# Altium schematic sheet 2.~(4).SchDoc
size 420 x 297 mm
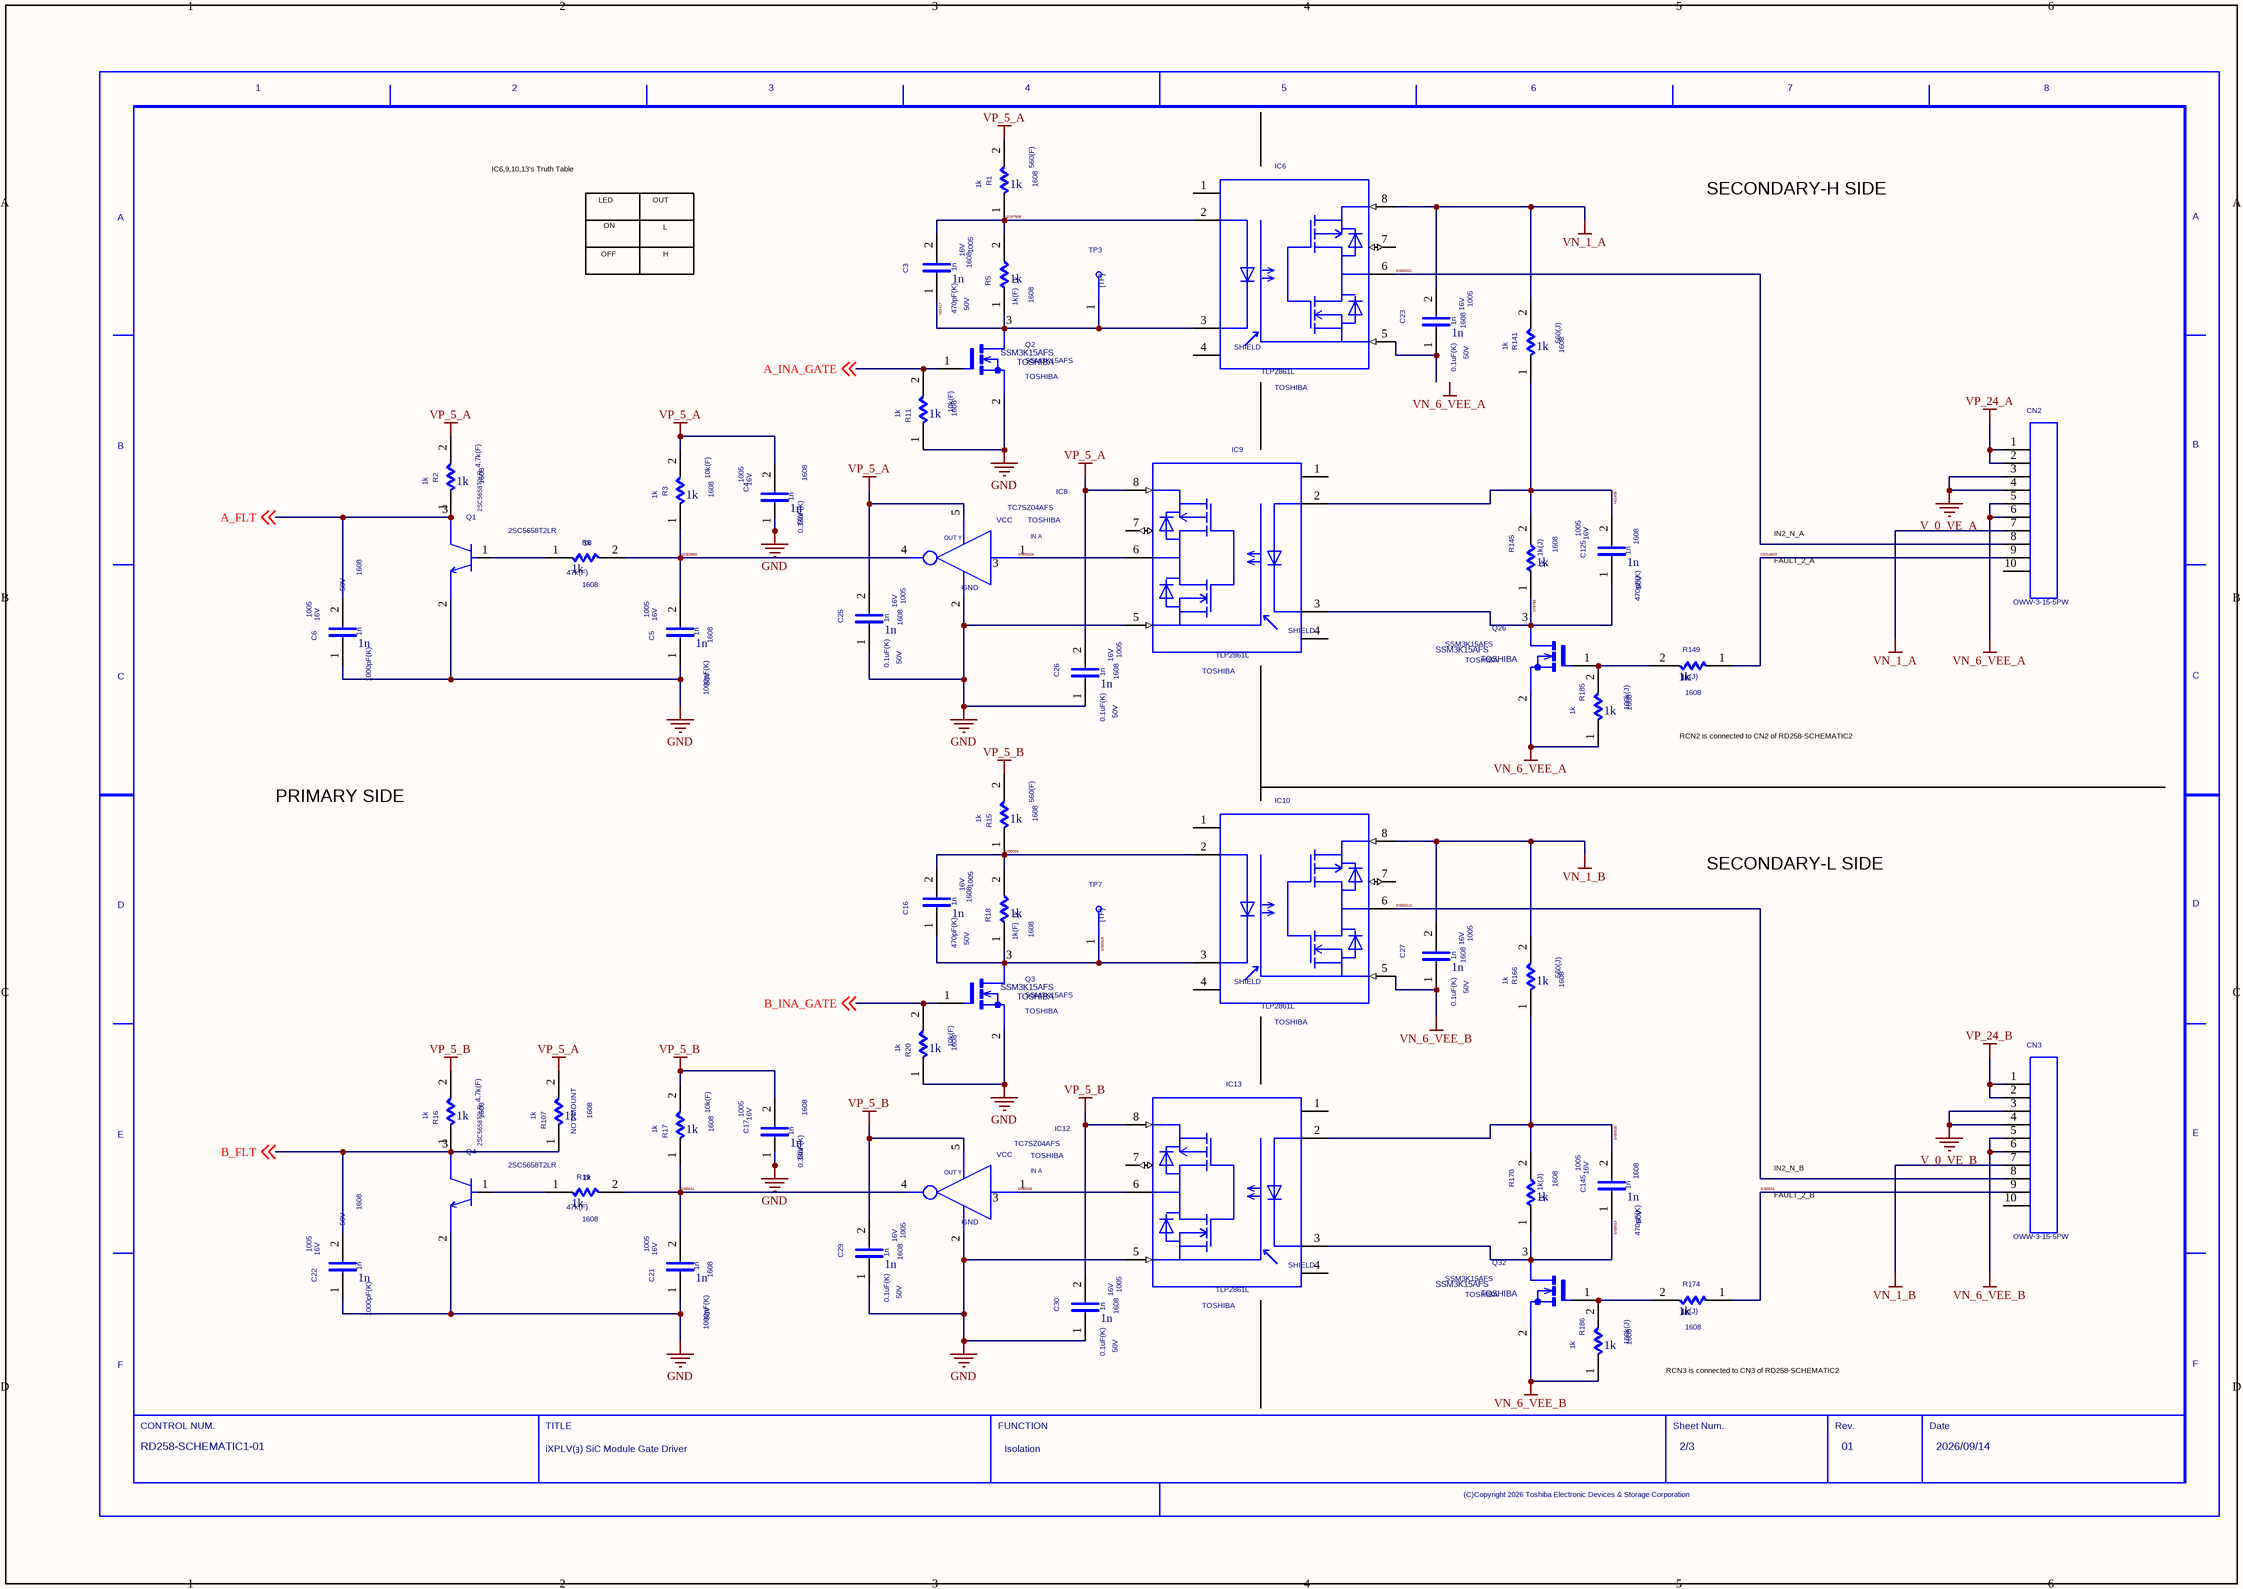
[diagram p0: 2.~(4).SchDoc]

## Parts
C3  1n  VAL1: 470pF(K)  SIZE: 1005  VOLTAGE: 16V  SIZECODESMD: 1608  VAL2: 50V
C4  1n  VAL1: 0.33uF(K)  SIZE: 1005  VOLTAGE: 16V  SIZECODESMD: 1608  VAL2: 50V
C5  1n  VAL1: 1000pF(K)  SIZE: 1005  VOLTAGE: 16V  SIZECODESMD: 1608  VAL2: 50V
C6  1n  VAL1: 1000pF(K)  SIZE: 1005  VOLTAGE: 16V  SIZECODESMD: 1608  VAL2: 50V
C16  1n  VAL1: 470pF(K)  SIZE: 1005  VOLTAGE: 16V  SIZECODESMD: 1608  VAL2: 50V
C17  1n  VAL1: 0.33uF(K)  SIZE: 1005  VOLTAGE: 16V  SIZECODESMD: 1608  VAL2: 50V
C21  1n  VAL1: 1000pF(K)  SIZE: 1005  VOLTAGE: 16V  SIZECODESMD: 1608  VAL2: 50V
C22  1n  VAL1: 1000pF(K)  SIZE: 1005  VOLTAGE: 16V  SIZECODESMD: 1608  VAL2: 50V
C23  1n  VAL1: 0.1uF(K)  SIZE: 1005  VOLTAGE: 16V  SIZECODESMD: 1608  VAL2: 50V
C25  1n  VAL1: 0.1uF(K)  SIZE: 1005  VOLTAGE: 16V  SIZECODESMD: 1608  VAL2: 50V
C26  1n  VAL1: 0.1uF(K)  SIZE: 1005  VOLTAGE: 16V  SIZECODESMD: 1608  VAL2: 50V
C27  1n  VAL1: 0.1uF(K)  SIZE: 1005  VOLTAGE: 16V  SIZECODESMD: 1608  VAL2: 50V
C29  1n  VAL1: 0.1uF(K)  SIZE: 1005  VOLTAGE: 16V  SIZECODESMD: 1608  VAL2: 50V
C30  1n  VAL1: 0.1uF(K)  SIZE: 1005  VOLTAGE: 16V  SIZECODESMD: 1608  VAL2: 50V
C125  1n  VAL1: 470pF(K)  SIZE: 1005  VOLTAGE: 16V  SIZECODESMD: 1608  VAL2: 50V
C145  1n  VAL1: 470pF(K)  SIZE: 1005  VOLTAGE: 16V  SIZECODESMD: 1608  VAL2: 50V
CN2  VAL3: OWW-3-15-5PW  (hidden comment: CN9_2)
CN3  VAL3: OWW-3-15-5PW  (hidden comment: CN9_2)
IC6  USERCOMPTEXT3: TOSHIBA  (hidden comment: TLP2861L)
IC8  USERCOMPTEXT3: TOSHIBA  (hidden comment: TC7SZ04AFS)
IC9  USERCOMPTEXT3: TOSHIBA  (hidden comment: TLP2861L)
IC10  USERCOMPTEXT3: TOSHIBA  (hidden comment: TLP2861L)
IC12  USERCOMPTEXT3: TOSHIBA  (hidden comment: TC7SZ04AFS)
IC13  USERCOMPTEXT3: TOSHIBA  (hidden comment: TLP2861L)
Q1  2SC5658T2LR
Q2  SSM3K15AFS  VENDOR: TOSHIBA
Q3  SSM3K15AFS  VENDOR: TOSHIBA
Q4  2SC5658T2LR
Q26  SSM3K15AFS  VENDOR: TOSHIBA
Q32  SSM3K15AFS  VENDOR: TOSHIBA
R1  1k  VAL1: 560(F)  SIZECODESMD: 1608
R2  1k  VAL1: 4.7k(F)  SIZECODESMD: 1608
R3  1k  VAL1: 10k(F)  SIZECODESMD: 1608
R5  1k  VAL1: 1k(F)  SIZECODESMD: 1608
R8  1k  VAL1: 47k(F)  SIZECODESMD: 1608
R11  1k  VAL1: 10k(F)  SIZECODESMD: 1608
R15  1k  VAL1: 560(F)  SIZECODESMD: 1608
R16  1k  VAL1: 4.7k(F)  SIZECODESMD: 1608
R17  1k  VAL1: 10k(F)  SIZECODESMD: 1608
R18  1k  VAL1: 1k(F)  SIZECODESMD: 1608
R19  1k  VAL1: 47k(F)  SIZECODESMD: 1608
R20  1k  VAL1: 10k(F)  SIZECODESMD: 1608
R107  1k  NOTMOUNT: NOT MOUNT  SIZECODESMD: 1608
R141  1k  VAL1: 560(J)  SIZECODESMD: 1608
R145  1k  VAL1: 1k(J)  SIZECODESMD: 1608
R149  1k  VAL1: 1k(J)  SIZECODESMD: 1608
R166  1k  VAL1: 560(J)  SIZECODESMD: 1608
R170  1k  VAL1: 1k(J)  SIZECODESMD: 1608
R174  1k  VAL1: 1k(J)  SIZECODESMD: 1608
R185  1k  VAL1: 100k(J)  SIZECODESMD: 1608
R186  1k  VAL1: 100k(J)  SIZECODESMD: 1608
TP3  TP  (value not drawn)
TP7  TP  (value not drawn)
U?  DATE: 2026/09/14  DRAWINGNUMBER: RD258-SCHEMATIC1-01  TITLE: iXPLV(ｮ) SiC Module Gate Driver  FUNCTION: Isolation  SHEETNUMBER: 2/3  REVISION: 01  (hidden comment: WAKU_DEF100)

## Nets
GND: C4.1 C5.1 C6.1 C17.1 C21.1 C22.1 C25.1 C26.1 C29.1 C30.1 IC8.2 IC9.5 IC12.2 IC13.5 Q1.2(E) Q2.2(S) Q3.2(S) Q4.2(E) R11.1 R20.1
V_0_VE_A: CN2.3 CN2.4
V_0_VE_B: CN3.3 CN3.4
VN_1_A: C23.2 CN2.7 IC6.8 R141.2
VN_1_B: C27.2 CN3.7 IC10.8 R166.2
VN_6_VEE_A: CN2.5 CN2.6 Q26.2(S) R185.1
VN_6_VEE_B: C27.1 CN3.5 CN3.6 IC10.5 Q32.2(S) R186.1
VP_5_A: C4.2 C25.2 C26.2 IC8.5 IC9.8 R1.2 R2.2 R3.2 R107.2
VP_5_B: C17.2 C29.2 C30.2 IC12.5 IC13.8 R15.2 R16.2 R17.2
VP_24_A: CN2.1 CN2.2
VP_24_B: CN3.1 CN3.2
A_FLT: C6.2 Q1.3(C) R2.1 ; off-sheet A_FLT
A_INA_GATE: Q2.1(G) R11.2 ; off-sheet A_INA_GATE
B_FLT: C22.2 Q4.3(C) R16.1 R107.1 ; off-sheet B_FLT
B_INA_GATE: Q3.1(G) R20.2 ; off-sheet B_INA_GATE
N02405: C125.2 IC9.2 R141.1 R145.2
N02417: C3.1 IC6.3 Q2.3(D) R5.1 TP3.1
N76786: C125.1 IC9.3 Q26.3(D) R145.1
N2014523: CN2.9 R149.1
N2053860: C5.2 IC8.4 R3.1 R8.2
N2197908: C3.2 IC6.2 R1.1 R5.2
SIG00005: Q1.1(B) R8.1
SIG0021: C21.2 IC12.4 R17.1 R19.2
SIG00021: CN2.8 IC6.6
SIG0022: Q32.1(G) R174.2 R186.2
SIG0023: C145.1 IC13.3 Q32.3(D) R170.1
SIG0024: CN3.9 R174.1
SIG0025: C145.2 IC13.2 R166.1 R170.2
SIG00026: IC8.1 IC9.6
SIG0026: C16.2 IC10.2 R15.1 R18.2
SIG0027: Q4.1(B) R19.1
SIG0028: IC12.1 IC13.6
SIG0029: C16.1 IC10.3 Q3.3(D) R18.1 TP7.1
SIG00190: Q26.1(G) R149.2 R185.2
SIG00210: CN3.8 IC10.6
NetC23_1: C23.1 IC6.5

Not connected (* = marked no-connect by the designer): CN2 10; CN3 10; IC6 1 4 7; IC8 3; IC9 1 4 7; IC10 1 4 7; IC12 3; IC13 1 4 7

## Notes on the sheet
- IC6,9,10,13's Truth Table
- LED
- OFF
- ON
- OUT
- H
- L
- SECONDARY-H SIDE
- IN2_N_A
- FAULT_2_A
- PRIMARY SIDE
- RCN2 is connected to CN2 of RD258-SCHEMATIC2
- SECONDARY-L SIDE
- FAULT_2_B
- IN2_N_B
- RCN3 is connected to CN3 of RD258-SCHEMATIC2
- Labels drawn without touching a wire or pin: VN_6_VEE_A

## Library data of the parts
C3 C16 = C: TIME: 11:55:01; UPDATEUSER: HP_Z8_KEYSHOT; SAVECOUNT: 2; TC1: 0; PSPICETEMPLATE: C^@REFDES %1 %2 ?TOLERANCE¦C^@REFDES¦ @VALUE ?IC/IC=@IC/ TC=@TC1,@TC2 ?TOLERANCE¦\n.model C^@REFDES CAP C=1 DEV=@TOLERANCE% TC1=@TC1 TC2=@TC2 VC1=@VC1 VC2=@VC2¦; ORIGINALSYMBOLORIGIN: (0,0); INSTANCENAME: INS2054894
C4 C17 = C: TIME: 11:55:01; UPDATEUSER: HP_Z8_KEYSHOT; SAVECOUNT: 2; TC1: 0; PSPICETEMPLATE: C^@REFDES %1 %2 ?TOLERANCE¦C^@REFDES¦ @VALUE ?IC/IC=@IC/ TC=@TC1,@TC2 ?TOLERANCE¦\n.model C^@REFDES CAP C=1 DEV=@TOLERANCE% TC1=@TC1 TC2=@TC2 VC1=@VC1 VC2=@VC2¦; ORIGINALSYMBOLORIGIN: (0,0); INSTANCENAME: INS2053830
C5 C6 C21 C22 = C: TIME: 11:55:01; UPDATEUSER: HP_Z8_KEYSHOT; SAVECOUNT: 2; TC1: 0; PSPICETEMPLATE: C^@REFDES %1 %2 ?TOLERANCE¦C^@REFDES¦ @VALUE ?IC/IC=@IC/ TC=@TC1,@TC2 ?TOLERANCE¦\n.model C^@REFDES CAP C=1 DEV=@TOLERANCE% TC1=@TC1 TC2=@TC2 VC1=@VC1 VC2=@VC2¦; ORIGINALSYMBOLORIGIN: (0,0); INSTANCENAME: INS2053916
C23 C27 = C: TIME: 11:55:01; UPDATEUSER: HP_Z8_KEYSHOT; SAVECOUNT: 2; TC1: 0; PSPICETEMPLATE: C^@REFDES %1 %2 ?TOLERANCE¦C^@REFDES¦ @VALUE ?IC/IC=@IC/ TC=@TC1,@TC2 ?TOLERANCE¦\n.model C^@REFDES CAP C=1 DEV=@TOLERANCE% TC1=@TC1 TC2=@TC2 VC1=@VC1 VC2=@VC2¦; ORIGINALSYMBOLORIGIN: (0,0); INSTANCENAME: INS1388174
C25 C26 C29 C30 = C: TIME: 11:55:01; UPDATEUSER: HP_Z8_KEYSHOT; SAVECOUNT: 2; TC1: 0; PSPICETEMPLATE: C^@REFDES %1 %2 ?TOLERANCE¦C^@REFDES¦ @VALUE ?IC/IC=@IC/ TC=@TC1,@TC2 ?TOLERANCE¦\n.model C^@REFDES CAP C=1 DEV=@TOLERANCE% TC1=@TC1 TC2=@TC2 VC1=@VC1 VC2=@VC2¦; ORIGINALSYMBOLORIGIN: (0,0); INSTANCENAME: INS1387946
C125 C145 = C: TIME: 11:55:01; UPDATEUSER: HP_Z8_KEYSHOT; SAVECOUNT: 2; TC1: 0; PSPICETEMPLATE: C^@REFDES %1 %2 ?TOLERANCE¦C^@REFDES¦ @VALUE ?IC/IC=@IC/ TC=@TC1,@TC2 ?TOLERANCE¦\n.model C^@REFDES CAP C=1 DEV=@TOLERANCE% TC1=@TC1 TC2=@TC2 VC1=@VC1 VC2=@VC2¦; ORIGINALSYMBOLORIGIN: (0,0); INSTANCENAME: INS2013765
CN2 CN3 = CN10_1: TIME: 08:48:13; UPDATEUSER: t5459927; UPDATETIME: 15:38:59; SAVECOUNT: 3; PSPICETEMPLATE: X^@REFDES %1 %2 %3 %4 %5 %6 %7 %8 %9 %10 %M1 %M2 @MODEL; USER_VALUE: XG4A-1031; OriginalSymbolOrigin: (0,0)
IC6 IC9 IC10 IC13 = TLP2861: TIME: 11:54:59; UPDATEUSER: t5459927; UPDATETIME: 10:22:13; SAVECOUNT: 4; PSPICETEMPLATE: X^@REFDES %1 %2 %3 %4 %5 %6 %7 %8 @MODEL; SAVEAREA0: -29717,-10800,67926,51382; OriginalSymbolOrigin: (5080,35560)
IC8 IC12 = TC7SZ04AFS: TIME: 11:55:02; UPDATEUSER: t5459927; UPDATETIME: 19:30:29; SAVECOUNT: 6; PSPICETEMPLATE: X^@REFDES %INA %GND %NC %OUTY %VCC @MODEL; OriginalSymbolOrigin: (0,-5080); INSTANCENAME: INS2077754
Q1 Q4 = 2SC5658J: TIME: 09:39:04; UPDATEUSER: 19910145; UPDATETIME: 15:12:10; SAVECOUNT: 8; VENDOR: ROHM; SAVEAREA0: -6194,-158,18648,15662; PSPICETEMPLATE: X^@REFDES %C %B %E @MODEL; ORIGINALSYMBOLORIGIN: (0,0); INSTANCENAME: INS2053972
Q2 Q3 = SSM3K15AFS: TIME: 11:54:59; UPDATEUSER: HP_Z8_KEYSHOT; UPDATETIME: 11:55:00; SAVECOUNT: 2; ORIGINALSYMBOLORIGIN: (0,0); PSPICETEMPLATE: X^@REFDES %D %G %S @MODEL; INSTANCENAME: INS2055002
Q26 Q32 = SSM3K15AFS: TIME: 11:54:59; UPDATEUSER: HP_Z8_KEYSHOT; UPDATETIME: 11:55:00; SAVECOUNT: 2; ORIGINALSYMBOLORIGIN: (0,0); PSPICETEMPLATE: X^@REFDES %D %G %S @MODEL; INSTANCENAME: INS2013847
R1-R3 R11 R15-R17 R20 = R_Dup1: TIME: 11:54:58; UPDATEUSER: HP_Z8_KEYSHOT; UPDATETIME: 11:54:59; SAVECOUNT: 2; WATT: 0.125; COMP: R; TC1: 0; PSPICETEMPLATE: R^@REFDES %1 %2 ?TOLERANCE¦R^@REFDES¦ @VALUE TC=@TC1,@TC2 ?TOLERANCE¦\n.model R^@REFDES RES R=1 DEV=@TOLERANCE% TC1=@TC1 TC2=@TC2¦; ORIGINALSYMBOLORIGIN: (0,0); VAL2: 100mW; INSTANCENAME: INS2053752
R5 R18 = R_Dup1: TIME: 11:54:58; UPDATEUSER: HP_Z8_KEYSHOT; UPDATETIME: 11:54:59; SAVECOUNT: 2; WATT: 0.125; COMP: R; TC1: 0; PSPICETEMPLATE: R^@REFDES %1 %2 ?TOLERANCE¦R^@REFDES¦ @VALUE TC=@TC1,@TC2 ?TOLERANCE¦\n.model R^@REFDES RES R=1 DEV=@TOLERANCE% TC1=@TC1 TC2=@TC2¦; ORIGINALSYMBOLORIGIN: (0,0); VAL2: 100mW; INSTANCENAME: INS2054922
R8 R19 = R_Dup1: TIME: 11:54:58; UPDATEUSER: HP_Z8_KEYSHOT; UPDATETIME: 11:54:59; SAVECOUNT: 2; WATT: 0.125; COMP: R; TC1: 0; PSPICETEMPLATE: R^@REFDES %1 %2 ?TOLERANCE¦R^@REFDES¦ @VALUE TC=@TC1,@TC2 ?TOLERANCE¦\n.model R^@REFDES RES R=1 DEV=@TOLERANCE% TC1=@TC1 TC2=@TC2¦; ORIGINALSYMBOLORIGIN: (0,0); VAL2: 100mW; INSTANCENAME: INS2053892
R107 = R_Dup1: TIME: 11:54:58; UPDATEUSER: HP_Z8_KEYSHOT; UPDATETIME: 11:54:59; SAVECOUNT: 2; WATT: 0.125; COMP: R; TC1: 0; PSPICETEMPLATE: R^@REFDES %1 %2 ?TOLERANCE¦R^@REFDES¦ @VALUE TC=@TC1,@TC2 ?TOLERANCE¦\n.model R^@REFDES RES R=1 DEV=@TOLERANCE% TC1=@TC1 TC2=@TC2¦; ORIGINALSYMBOLORIGIN: (0,0); INSTANCENAME: INS2053752
R141 R166 = R_Dup1: TIME: 11:54:58; UPDATEUSER: HP_Z8_KEYSHOT; UPDATETIME: 11:54:59; SAVECOUNT: 2; WATT: 0.125; COMP: R; TC1: 0; PSPICETEMPLATE: R^@REFDES %1 %2 ?TOLERANCE¦R^@REFDES¦ @VALUE TC=@TC1,@TC2 ?TOLERANCE¦\n.model R^@REFDES RES R=1 DEV=@TOLERANCE% TC1=@TC1 TC2=@TC2¦; ORIGINALSYMBOLORIGIN: (0,0); VAL2: 100mW; INSTANCENAME: INS2013711
R145 R149 R170 R174 = R_Dup1: TIME: 11:54:58; UPDATEUSER: HP_Z8_KEYSHOT; UPDATETIME: 11:54:59; SAVECOUNT: 2; WATT: 0.125; COMP: R; TC1: 0; PSPICETEMPLATE: R^@REFDES %1 %2 ?TOLERANCE¦R^@REFDES¦ @VALUE TC=@TC1,@TC2 ?TOLERANCE¦\n.model R^@REFDES RES R=1 DEV=@TOLERANCE% TC1=@TC1 TC2=@TC2¦; ORIGINALSYMBOLORIGIN: (0,0); VAL2: 100mW; INSTANCENAME: INS2013869
R185 R186 = R_Dup1: TIME: 11:54:58; UPDATEUSER: HP_Z8_KEYSHOT; UPDATETIME: 11:54:59; SAVECOUNT: 2; WATT: 0.125; COMP: R; TC1: 0; PSPICETEMPLATE: R^@REFDES %1 %2 ?TOLERANCE¦R^@REFDES¦ @VALUE TC=@TC1,@TC2 ?TOLERANCE¦\n.model R^@REFDES RES R=1 DEV=@TOLERANCE% TC1=@TC1 TC2=@TC2¦; ORIGINALSYMBOLORIGIN: (0,0); VAL2: 100mW; INSTANCENAME: INS2014404
TP3 TP7 = TP: TIME: 16:12:21; UPDATEUSER: fukuda-y; UPDATETIME: 16:18:11; SAVECOUNT: 2; SAVEAREA0: -242,-92,12810,7836; ORIGINALSYMBOLORIGIN: (0,0); INSTANCENAME: INS2054950
U? = WAKU_DEF100: PLOTTIME: HH:MM; SAVEAREA0: -63393,-16950,474261,314592; TIME: 14:30:25; UPDATEUSER: d5009410; UPDATETIME: 15:37:05; SAVECOUNT: 4; OriginalSymbolOrigin: (10160,284480); SHTSAVECOUNT: 40; NUMBER DEVICES IN PACKAGE: 1; SHEET NUM: X/X; PIN NUMBERS VISIBLE: False; CONTROL NUM: RD256-SCHEMATIC-0; PIN NAMES ROTATE: True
